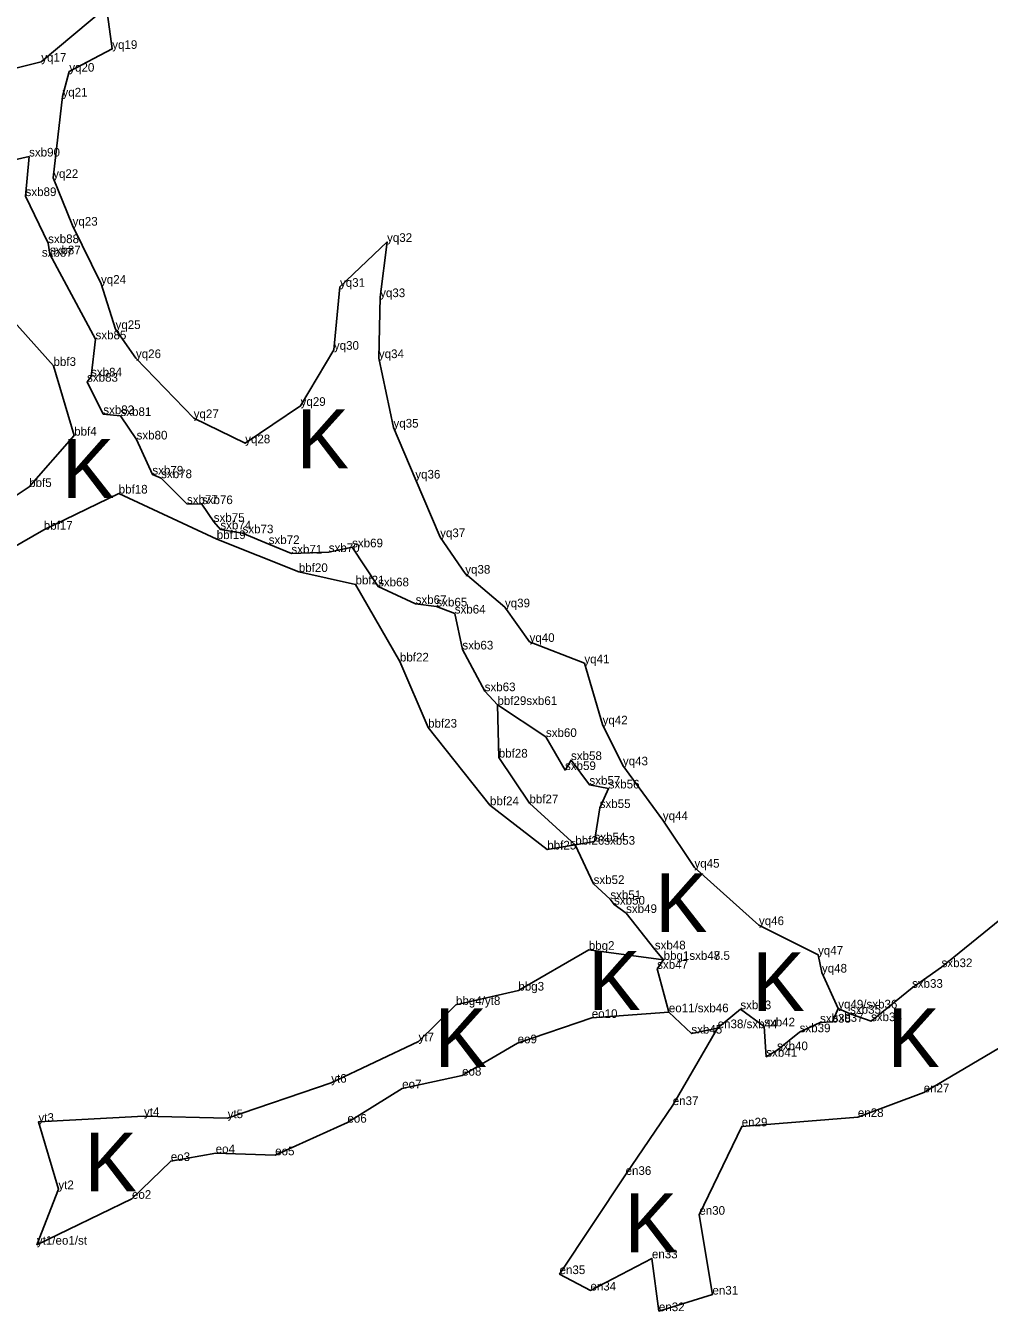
# Model space of a CAD drawing. Extents: x 2072529 to 2268812, y 436423 to 470008.
# Drawn here: x 2247027 to 2247584, y 439259 to 440002 of the extents above; entities that cross this region are included whole.
import ezdxf

# ---------------------------------------------------------------- set-up
doc = ezdxf.new("R2010")
doc.units = 0
for name, color, linetype in [('Old_Level_10', 7, 'Continuous'), ('Old_Level_20', 7, 'Continuous'), ('Old_Level_52', 7, 'Continuous'), ('Old_Level_55', 7, 'Continuous'), ('Old_Level_60', 7, 'Continuous')]:
    doc.layers.add(name, color=color, linetype=linetype)

msp = doc.modelspace()

# ---------------------------------------------------------------- linework, layer by layer
at = {"layer": 'Old_Level_10'}
for points in [[(2247004.359, 439920.906), (2247029.039, 439926.419), (2247026.981, 439903.545), (2247040.045, 439876.322), (2247041.025, 439869.854), (2247067.431, 439820.712), (2247064.88, 439799.216), (2247062.555, 439796.17), (2247071.911, 439777.444), (2247081.868, 439776.361), (2247091.169, 439762.771), (2247100.333, 439742.483), (2247105.371, 439740.4), (2247120.299, 439725.552), (2247128.961, 439725.379), (2247135.779, 439715.122), (2247139.626, 439710.738), (2247152.44, 439708.505), (2247167.57, 439702.28), (2247180.71, 439696.796), (2247202.307, 439697.65), (2247215.806, 439700.41), (2247230.804, 439677.822), (2247252.526, 439667.657), (2247264.534, 439666.193), (2247275.128, 439662.106), (2247279.569, 439641.304), (2247292.443, 439617.172), (2247299.798, 439609.217), (2247327.845, 439590.712)], [(2247327.845, 439590.712), (2247338.896, 439571.586), (2247342.364, 439577.354), (2247353.017, 439563.049), (2247364.124, 439560.935), (2247358.936, 439549.624), (2247355.952, 439530.273), (2247344.838, 439528.389), (2247355.409, 439505.676), (2247365.09, 439496.946), (2247367.26, 439493.733), (2247374.213, 439488.891), (2247390.812, 439467.828), (2247395.908, 439461.8), (2247392.175, 439456.618), (2247398.926, 439431.481), (2247411.945, 439419.135), (2247427.148, 439422.283), (2247440.264, 439433.261), (2247454.03, 439423.342), (2247455.24, 439405.773), (2247461.465, 439409.544), (2247474.547, 439419.91), (2247486.347, 439425.506), (2247493.629, 439425.967), (2247496.857, 439433.688), (2247503.698, 439430.626), (2247515.812, 439426.342), (2247539.517, 439445.631), (2247556.597, 439457.577), (2247594.289, 439488.192)]]:
    msp.add_lwpolyline(points, dxfattribs=at)
at = {"layer": 'Old_Level_20'}
for p, q in [((2247077.099, 439988.662), (2247077.099, 439988.662)), ((2247036.067, 439981.256), (2247036.067, 439981.256)), ((2247052.259, 439975.499), (2247052.259, 439975.499)), ((2247048.312, 439961.133), (2247048.312, 439961.133)), ((2247029.039, 439926.419), (2247029.039, 439926.419)), ((2247042.944, 439914.035), (2247042.944, 439914.035)), ((2247054.184, 439886.442), (2247054.184, 439886.442)), ((2247040.045, 439876.322), (2247040.045, 439876.322)), ((2247236.004, 439877.038), (2247236.004, 439877.038)), ((2247036.424, 439868.487), (2247036.424, 439868.487)), ((2247041.025, 439869.854), (2247041.025, 439869.854)), ((2247070.606, 439852.852), (2247070.606, 439852.852)), ((2247208.779, 439851.061), (2247208.779, 439851.061)), ((2247231.988, 439845.098), (2247231.988, 439845.098)), ((2247079.012, 439826.657), (2247079.012, 439826.657)), ((2247067.431, 439820.712), (2247067.431, 439820.712)), ((2247205.244, 439814.657), (2247205.244, 439814.657)), ((2247090.804, 439809.826), (2247090.804, 439809.826)), ((2247231.253, 439809.829), (2247231.253, 439809.829)), ((2247043.137, 439805.319), (2247043.137, 439805.319)), ((2247062.555, 439796.17), (2247062.555, 439796.17)), ((2247064.88, 439799.216), (2247064.88, 439799.216)), ((2247071.911, 439777.444), (2247071.911, 439777.444)), ((2247186.02, 439782.21), (2247186.02, 439782.21)), ((2247081.868, 439776.361), (2247081.868, 439776.361)), ((2247124.196, 439775.11), (2247124.196, 439775.11)), ((2247055.113, 439764.997), (2247055.113, 439764.997)), ((2247091.169, 439762.771), (2247091.169, 439762.771)), ((2247239.703, 439769.661), (2247239.703, 439769.661)), ((2247153.949, 439760.586), (2247153.949, 439760.586)), ((2247100.333, 439742.483), (2247100.333, 439742.483)), ((2247105.371, 439740.4), (2247105.371, 439740.4)), ((2247252.324, 439740.154), (2247252.324, 439740.154)), ((2247029.083, 439735.301), (2247029.083, 439735.301)), ((2247080.821, 439731.498), (2247080.821, 439731.498)), ((2247120.299, 439725.552), (2247120.299, 439725.552)), ((2247128.961, 439725.379), (2247128.961, 439725.379)), ((2247037.506, 439710.572), (2247037.506, 439710.572)), ((2247135.779, 439715.122), (2247135.779, 439715.122)), ((2247139.626, 439710.738), (2247139.626, 439710.738)), ((2247137.501, 439705.17), (2247137.501, 439705.17)), ((2247152.44, 439708.505), (2247152.44, 439708.505)), ((2247266.688, 439706.281), (2247266.688, 439706.281)), ((2247167.57, 439702.28), (2247167.57, 439702.28)), ((2247180.71, 439696.796), (2247180.71, 439696.796)), ((2247202.307, 439697.65), (2247202.307, 439697.65)), ((2247215.806, 439700.41), (2247215.806, 439700.41)), ((2247184.983, 439686.131), (2247184.983, 439686.131)), ((2247281.213, 439685.155), (2247281.213, 439685.155)), ((2247217.79, 439678.96), (2247217.79, 439678.96)), ((2247230.804, 439677.822), (2247230.804, 439677.822)), ((2247252.526, 439667.657), (2247252.526, 439667.657)), ((2247264.534, 439666.193), (2247264.534, 439666.193)), ((2247304.153, 439665.687), (2247304.153, 439665.687)), ((2247275.128, 439662.106), (2247275.128, 439662.106)), ((2247318.379, 439645.688), (2247318.379, 439645.688)), ((2247279.569, 439641.304), (2247279.569, 439641.304)), ((2247243.436, 439634.357), (2247243.436, 439634.357)), ((2247350.091, 439633.299), (2247350.091, 439633.299)), ((2247292.443, 439617.172), (2247292.443, 439617.172)), ((2247299.798, 439609.217), (2247299.798, 439609.217)), ((2247299.798, 439609.217), (2247299.798, 439609.217)), ((2247259.712, 439596.12), (2247259.712, 439596.12)), ((2247360.612, 439597.996), (2247360.612, 439597.996)), ((2247327.845, 439590.712), (2247327.845, 439590.712)), ((2247300.569, 439578.796), (2247300.569, 439578.796)), ((2247342.364, 439577.354), (2247342.364, 439577.354)), ((2247338.896, 439571.586), (2247338.896, 439571.586)), ((2247372.359, 439574.299), (2247372.359, 439574.299)), ((2247353.017, 439563.049), (2247353.017, 439563.049)), ((2247364.124, 439560.935), (2247364.124, 439560.935)), ((2247295.51, 439551.229), (2247295.51, 439551.229)), ((2247318.308, 439552.346), (2247318.308, 439552.346)), ((2247358.936, 439549.624), (2247358.936, 439549.624)), ((2247395.449, 439542.627), (2247395.449, 439542.627)), ((2247328.635, 439525.617), (2247328.635, 439525.617)), ((2247344.838, 439528.389), (2247344.838, 439528.389)), ((2247344.838, 439528.389), (2247344.838, 439528.389)), ((2247355.952, 439530.273), (2247355.952, 439530.273)), ((2247413.722, 439515.116), (2247413.722, 439515.116)), ((2247355.409, 439505.676), (2247355.409, 439505.676)), ((2247365.09, 439496.946), (2247365.09, 439496.946)), ((2247367.26, 439493.733), (2247367.26, 439493.733)), ((2247374.213, 439488.891), (2247374.213, 439488.891)), ((2247451.011, 439481.891), (2247451.011, 439481.891)), ((2247352.626, 439467.59), (2247352.626, 439467.59)), ((2247390.812, 439467.828), (2247390.812, 439467.828)), ((2247395.908, 439461.8), (2247395.908, 439461.8)), ((2247395.908, 439461.8), (2247395.908, 439461.8)), ((2247485.182, 439464.772), (2247485.182, 439464.772)), ((2247556.597, 439457.577), (2247556.597, 439457.577)), ((2247392.175, 439456.618), (2247392.175, 439456.618)), ((2247487.437, 439454.449), (2247487.437, 439454.449)), ((2247311.901, 439444.022), (2247311.901, 439444.022)), ((2247539.517, 439445.631), (2247539.517, 439445.631)), ((2247275.841, 439435.692), (2247275.841, 439435.692)), ((2247354.352, 439428.181), (2247354.352, 439428.181)), ((2247398.926, 439431.481), (2247398.926, 439431.481)), ((2247398.926, 439431.481), (2247398.926, 439431.481)), ((2247440.264, 439433.261), (2247440.264, 439433.261)), ((2247496.857, 439433.688), (2247496.857, 439433.688)), ((2247496.857, 439433.688), (2247496.857, 439433.688)), ((2247503.698, 439430.626), (2247503.698, 439430.626)), ((2247427.148, 439422.283), (2247427.148, 439422.283)), ((2247427.148, 439422.283), (2247427.148, 439422.283)), ((2247454.03, 439423.342), (2247454.03, 439423.342)), ((2247486.347, 439425.506), (2247486.347, 439425.506)), ((2247493.629, 439425.967), (2247493.629, 439425.967)), ((2247515.812, 439426.342), (2247515.812, 439426.342)), ((2247254.224, 439414.655), (2247254.224, 439414.655)), ((2247311.492, 439413.521), (2247311.492, 439413.521)), ((2247411.945, 439419.135), (2247411.945, 439419.135)), ((2247474.547, 439419.91), (2247474.547, 439419.91)), ((2247455.24, 439405.773), (2247455.24, 439405.773)), ((2247461.465, 439409.544), (2247461.465, 439409.544)), ((2247203.701, 439390.755), (2247203.701, 439390.755)), ((2247279.385, 439394.843), (2247279.385, 439394.843)), ((2247244.735, 439387.421), (2247244.735, 439387.421)), ((2247546.259, 439385.16), (2247546.259, 439385.16)), ((2247401.164, 439377.802), (2247401.164, 439377.802)), ((2247095.452, 439371.463), (2247095.452, 439371.463)), ((2247143.814, 439370.234), (2247143.814, 439370.234)), ((2247508.211, 439370.895), (2247508.211, 439370.895)), ((2247034.455, 439368.094), (2247034.455, 439368.094)), ((2247213.089, 439367.637), (2247213.089, 439367.637)), ((2247441.029, 439365.468), (2247441.029, 439365.468)), ((2247136.9, 439349.961), (2247136.9, 439349.961)), ((2247171.31, 439348.747), (2247171.31, 439348.747)), ((2247110.949, 439345.446), (2247110.949, 439345.446)), ((2247373.91, 439337.419), (2247373.91, 439337.419)), ((2247045.966, 439329.165), (2247045.966, 439329.165)), ((2247088.494, 439323.579), (2247088.494, 439323.579)), ((2247416.534, 439314.358), (2247416.534, 439314.358)), ((2247033.535, 439297.065), (2247033.535, 439297.065)), ((2247389.136, 439289.158), (2247389.136, 439289.158)), ((2247335.731, 439280.04), (2247335.731, 439280.04)), ((2247353.583, 439270.562), (2247353.583, 439270.562)), ((2247424.125, 439268.204), (2247424.125, 439268.204)), ((2247393.166, 439258.604), (2247393.166, 439258.604))]:
    msp.add_line(p, q, dxfattribs=at)
at = {"layer": 'Old_Level_52'}
for points in [[(2247003.925, 439973.249), (2247036.067, 439981.256), (2247073.805, 440012.795), (2247077.099, 439988.662), (2247052.259, 439975.499), (2247048.312, 439961.133), (2247042.944, 439914.035), (2247054.184, 439886.442), (2247070.606, 439852.852), (2247079.012, 439826.657), (2247090.804, 439809.826), (2247124.196, 439775.11), (2247153.949, 439760.586), (2247186.02, 439782.21), (2247205.244, 439814.657), (2247208.779, 439851.061), (2247236.004, 439877.038), (2247231.988, 439845.098), (2247231.253, 439809.829), (2247239.703, 439769.661), (2247252.324, 439740.154), (2247266.688, 439706.281), (2247281.213, 439685.155), (2247304.153, 439665.687), (2247318.379, 439645.688), (2247350.091, 439633.299), (2247360.612, 439597.996), (2247372.359, 439574.299), (2247395.449, 439542.627), (2247413.722, 439515.116), (2247451.011, 439481.891), (2247485.182, 439464.772), (2247487.437, 439454.449), (2247496.857, 439433.688)], [(2247012.36, 439839.915), (2247043.137, 439805.319), (2247055.113, 439764.997), (2247029.083, 439735.301), (2246988.346, 439708.395)], [(2246999.286, 439688.436), (2247037.506, 439710.572), (2247080.821, 439731.498), (2247137.501, 439705.17), (2247184.983, 439686.131), (2247217.79, 439678.96), (2247243.436, 439634.357), (2247259.712, 439596.12), (2247295.51, 439551.229), (2247328.635, 439525.617), (2247344.838, 439528.389), (2247318.308, 439552.346), (2247300.569, 439578.796), (2247299.798, 439609.217)], [(2247395.908, 439461.8), (2247352.626, 439467.59), (2247311.901, 439444.022), (2247275.841, 439435.692), (2247254.224, 439414.655), (2247203.701, 439390.755), (2247143.814, 439370.234), (2247095.452, 439371.463), (2247034.455, 439368.094), (2247045.966, 439329.165), (2247033.535, 439297.065), (2247088.494, 439323.579), (2247110.949, 439345.446), (2247136.9, 439349.961), (2247171.31, 439348.747), (2247213.089, 439367.637), (2247244.735, 439387.421), (2247279.385, 439394.843), (2247311.492, 439413.521), (2247354.352, 439428.181), (2247398.926, 439431.481)], [(2247427.148, 439422.283), (2247401.164, 439377.802), (2247373.91, 439337.419), (2247335.731, 439280.04), (2247353.583, 439270.562), (2247389.136, 439289.158), (2247393.166, 439258.604), (2247424.125, 439268.204), (2247416.534, 439314.358), (2247441.029, 439365.468), (2247508.211, 439370.895), (2247546.259, 439385.16), (2247597.569, 439415.414)]]:
    msp.add_lwpolyline(points, dxfattribs=at)

# ---------------------------------------------------------------- texts
at = {"layer": 'Old_Level_55'}
for p in [(2247183.65, 439746.12), (2247047.954, 439728.989), (2247390.957, 439477.828), (2247352.221, 439432.844), (2247447.188, 439432.219), (2247263.503, 439399.731), (2247525.285, 439399.731), (2247061.075, 439327.882), (2247373.384, 439292.683)]:
    msp.add_text('K', height=34, dxfattribs=at).set_placement(p)
at = {"layer": 'Old_Level_60'}
for s, p in [('yq19', (2247077.099, 439988.662)), ('yq17', (2247036.067, 439981.256)), ('yq20', (2247052.259, 439975.499)), ('yq21', (2247048.312, 439961.133)), ('sxb90', (2247029.039, 439926.419)), ('yq22', (2247042.944, 439914.035)), ('sxb89', (2247026.981, 439903.545)), ('yq23', (2247054.184, 439886.442)), ('sxb88', (2247040.045, 439876.322)), ('yq32', (2247236.004, 439877.038)), ('sxb87', (2247041.025, 439869.854)), ('sxb87', (2247036.424, 439868.487)), ('yq24', (2247070.606, 439852.852)), ('yq31', (2247208.779, 439851.061)), ('yq33', (2247231.988, 439845.098)), ('yq25', (2247079.012, 439826.657)), ('sxb85', (2247067.431, 439820.712)), ('yq26', (2247090.804, 439809.826)), ('yq30', (2247205.244, 439814.657)), ('yq34', (2247231.253, 439809.829)), ('bbf3', (2247043.137, 439805.319)), ('sxb83', (2247062.555, 439796.17)), ('sxb84', (2247064.88, 439799.216)), ('yq29', (2247186.02, 439782.21)), ('sxb82', (2247071.911, 439777.444)), ('sxb81', (2247081.868, 439776.361)), ('yq27', (2247124.196, 439775.11)), ('bbf4', (2247055.113, 439764.997)), ('yq35', (2247239.703, 439769.661)), ('sxb80', (2247091.169, 439762.771)), ('yq28', (2247153.949, 439760.586)), ('sxb79', (2247100.333, 439742.483)), ('bbf5', (2247029.083, 439735.301)), ('sxb78', (2247105.371, 439740.4)), ('yq36', (2247252.324, 439740.154)), ('bbf18', (2247080.821, 439731.498)), ('sxb77', (2247120.299, 439725.552)), ('sxb76', (2247128.961, 439725.379)), ('sxb75', (2247135.779, 439715.122)), ('bbf17', (2247037.506, 439710.572)), ('bbf19', (2247137.501, 439705.17)), ('sxb74', (2247139.626, 439710.738)), ('sxb73', (2247152.44, 439708.505)), ('yq37', (2247266.688, 439706.281)), ('sxb72', (2247167.57, 439702.28)), ('sxb70', (2247202.307, 439697.65)), ('sxb69', (2247215.806, 439700.41)), ('sxb71', (2247180.71, 439696.796)), ('bbf20', (2247184.983, 439686.131)), ('yq38', (2247281.213, 439685.155)), ('bbf21', (2247217.79, 439678.96)), ('sxb68', (2247230.804, 439677.822)), ('sxb67', (2247252.526, 439667.657)), ('sxb65', (2247264.534, 439666.193)), ('sxb64', (2247275.128, 439662.106)), ('yq39', (2247304.153, 439665.687)), ('sxb63', (2247279.569, 439641.304)), ('yq40', (2247318.379, 439645.688)), ('bbf22', (2247243.436, 439634.357)), ('yq41', (2247350.091, 439633.299)), ('sxb63', (2247292.443, 439617.172)), ('bbf29sxb61', (2247299.798, 439609.217)), ('bbf29sxb61', (2247299.798, 439609.217)), ('bbf23', (2247259.712, 439596.12)), ('yq42', (2247360.612, 439597.996)), ('sxb60', (2247327.845, 439590.712)), ('bbf28', (2247300.569, 439578.796)), ('sxb59', (2247338.896, 439571.586)), ('sxb58', (2247342.364, 439577.354)), ('yq43', (2247372.359, 439574.299)), ('sxb57', (2247353.017, 439563.049)), ('sxb56', (2247364.124, 439560.935)), ('bbf24', (2247295.51, 439551.229)), ('bbf27', (2247318.308, 439552.346)), ('sxb55', (2247358.936, 439549.624)), ('yq44', (2247395.449, 439542.627)), ('bbf26sxb53', (2247344.838, 439528.389)), ('bbf26sxb53', (2247344.838, 439528.389)), ('sxb54', (2247355.952, 439530.273)), ('bbf25', (2247328.635, 439525.617)), ('yq45', (2247413.722, 439515.116)), ('sxb52', (2247355.409, 439505.676)), ('sxb51', (2247365.09, 439496.946)), ('sxb50', (2247367.26, 439493.733)), ('sxb49', (2247374.213, 439488.891)), ('yq46', (2247451.011, 439481.891)), ('bbg2', (2247352.626, 439467.59)), ('sxb48', (2247390.812, 439467.828)), ('bbg1sxb48.', (2247395.908, 439461.8)), ('bbg1sxb47.5', (2247395.908, 439461.8)), ('yq47', (2247485.182, 439464.772)), ('sxb47', (2247392.175, 439456.618)), ('yq48', (2247487.437, 439454.449)), ('sxb32', (2247556.597, 439457.577)), ('sxb33', (2247539.517, 439445.631)), ('bbg3', (2247311.901, 439444.022)), ('bbg4/yt8', (2247275.841, 439435.692)), ('eo11/sxb46', (2247398.926, 439431.481)), ('eo11/sxb46', (2247398.926, 439431.481)), ('sxb43', (2247440.264, 439433.261)), ('yq49/sxb36', (2247496.857, 439433.688)), ('yq49/sxb36', (2247496.857, 439433.688)), ('sxb35', (2247503.698, 439430.626)), ('eo10', (2247354.352, 439428.181)), ('sxb42', (2247454.03, 439423.342)), ('sxb38', (2247486.347, 439425.506)), ('sxb37', (2247493.629, 439425.967)), ('sxb34', (2247515.812, 439426.342)), ('sxb45', (2247411.945, 439419.135)), ('en38/sxb44', (2247427.148, 439422.283)), ('en38/sxb44', (2247427.148, 439422.283)), ('sxb39', (2247474.547, 439419.91)), ('yt7', (2247254.224, 439414.655)), ('eo9', (2247311.492, 439413.521)), ('sxb40', (2247461.465, 439409.544)), ('sxb41', (2247455.24, 439405.773)), ('eo8', (2247279.385, 439394.843)), ('yt6', (2247203.701, 439390.755)), ('eo7', (2247244.735, 439387.421)), ('en27', (2247546.259, 439385.16)), ('yt4', (2247095.452, 439371.463)), ('en37', (2247401.164, 439377.802)), ('en28', (2247508.211, 439370.895)), ('yt3', (2247034.455, 439368.094)), ('yt5', (2247143.814, 439370.234)), ('eo6', (2247213.089, 439367.637)), ('en29', (2247441.029, 439365.468)), ('eo4', (2247136.9, 439349.961)), ('eo5', (2247171.31, 439348.747)), ('eo3', (2247110.949, 439345.446)), ('en36', (2247373.91, 439337.419)), ('yt2', (2247045.966, 439329.165)), ('eo2', (2247088.494, 439323.579)), ('en30', (2247416.534, 439314.358)), ('yt1/eo1/st', (2247033.535, 439297.065)), ('en33', (2247389.136, 439289.158)), ('en35', (2247335.731, 439280.04)), ('en34', (2247353.583, 439270.562)), ('en31', (2247424.125, 439268.204)), ('en32', (2247393.166, 439258.604))]:
    msp.add_text(s, height=5, dxfattribs=at).set_placement(p)

doc.saveas('drawing.dxf')
